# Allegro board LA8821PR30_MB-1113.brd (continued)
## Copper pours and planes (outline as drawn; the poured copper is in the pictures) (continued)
LG_5V on IN3 (solid shape): 199.07,56.32 199.07,55.16 198,54.09 195.78,54.09 195.78,55.02 195.85,55.09 196.77,55.09 196.83,55.15 196.88,55.16 196.93,55.17 196.99,55.19 197.04,55.21 197.08,55.25 197.12,55.29 197.15,55.33 197.16,55.35 197.95,55.35 197.95,55.29 197.96,55.24 197.97,55.19 198,55.14 198.03,55.1 198.06,55.06 198.1,55.02 198.15,55 198.2,54.98 198.25,54.97 198.3,54.96 198.36,54.97 198.41,54.98 198.46,55 198.51,55.02 198.55,55.06 198.58,55.1 198.61,55.14 198.64,55.19 198.65,55.24 198.66,55.29 198.66,55.35 198.65,55.4 198.64,55.45 198.61,55.5 198.58,55.54 198.55,55.58 198.51,55.61 198.46,55.64 198.41,55.66 198.36,55.67 198.3,55.68 198.25,55.67 198.2,55.66 198.15,55.64 198.1,55.61 198.06,55.58 198.03,55.54 198,55.5 197.97,55.45 197.96,55.4 197.95,55.35 197.16,55.35 197.18,55.38 197.2,55.44 197.21,55.49 197.21,55.54 197.34,55.66 197.34,56.73 197.49,56.88 198.51,56.88
LG_+V1.05S_VCCPP on TOP (solid shape): 117.74,49.85 117.74,48.17 117.53,47.97 117.28,47.97 116.72,48.53 116.26,48.53 116.11,48.68 116.11,49.8 116.42,50.1 117.48,50.1
LG_+V1.05S_VCCPP on TOP (solid shape): 124.31,45.35 124.31,44.63 124.23,44.54 124.23,43.94 124.06,43.78 123.27,43.78 123.07,43.98 123.07,45 123.5,45.43 124.24,45.43
LG_+V1.05S_VCCPP on IN4 (solid shape): 124.34,44.89 124.34,43.93 124.19,43.78 123.07,43.78 122.89,43.95 122.89,45.28 123.07,45.45 123.78,45.45
LG_+V1.05S_VCCPP on IN4 (solid shape): 116.91,49.73 117.42,49.73 117.58,49.57 117.58,49.06 117.74,48.91 117.74,48.63 117.66,48.55 116.19,48.55 116.09,48.65 116.09,49.57 116.26,49.75 116.9,49.75
LGATE on TOP (solid shape): 139.88,32.73 139.88,31.48 138.46,31.48 138.28,31.66 138.28,32.68 138.49,32.88 139.73,32.88
LGATE on BOTTOM (solid shape): 147.25,35.94 147.25,35.09 147.17,35.01 146.57,35.01 146.47,35.09 146.35,35.17 146.01,35.52 146.01,35.93 146.12,36.04 147.15,36.04
LGATE on IN4 (solid shape): 140.49,33.49 140.49,32.83 139.91,32.25 138.56,32.25 138.39,32.42 138.39,32.7 139.38,33.69 140.29,33.69
LGATE on IN4 (solid shape): 146.92,35.67 146.92,35.14 146.21,34.43 145.73,34.43 145.5,34.66 145.5,35.42 145.65,35.57 145.67,35.58 145.86,35.68 145.96,35.87 145.96,35.89 146.13,36.06 146.54,36.06
LGATE1 on TOP (solid shape): 25.71,65.49 26.85,65.49 26.98,65.37 26.98,65.11 26.6,64.73 24.57,64.73 24.49,64.81 24.49,65.39 24.85,65.75 25.46,65.75
LGATE1 on BOTTOM (solid shape): 24.72,78.5 24.72,77.33 25.48,76.57 25.48,76.21 25.36,76.09 25.05,76.09 24.87,76.26 24.87,76.62 24.65,76.85 24.65,76.97 24.47,77.15 24.47,78.52 24.49,78.55 24.67,78.55
LGATE1 on IN2 (solid shape): 26.47,65.49 26.47,64.86 26.19,64.58 24.65,64.58 24.49,64.73 24.49,65.54 24.57,65.62 26.35,65.62
LGATE1 on IN2 (solid shape): 26.04,75.98 26.04,75.4 25.79,75.15 25.13,75.15 24.87,75.4 24.87,76.64 24.65,76.87 24.65,77.08 24.7,77.13 24.9,77.13
LGATE1G on TOP (solid shape): 24.85,69.94 24.85,69.18 24.75,69.08 24.62,69.08 24.19,68.64 23.53,68.64 23.32,68.85 23.32,69.86 23.5,70.04 24.75,70.04
LGATE1G on BOTTOM (solid shape): 20.07,80.3 20.12,80.3 20.15,80.3 20.17,80.29 20.39,80.06 21.53,80.06 21.57,80.02 21.57,79.9 21.5,79.82 19.97,79.82 19.59,79.44 19.36,79.44 19.26,79.54 19.26,79.79 19.77,80.3 20.02,80.3
LGATE1G on IN2 (solid shape): 24.85,70.98 24.85,69.63 24.49,69.28 23.48,69.28 23.35,69.41 23.35,70.7 23.76,71.11 24.72,71.11
LGATE1G on IN2 (solid shape): 20.48,80.18 21.77,80.18 21.85,80.1 21.85,79.44 21.77,79.36 19.39,79.36 19.21,79.54 19.21,79.79 19.69,80.28 20.38,80.28
LX_3V on TOP (solid shape): 189.78,56.41 189.78,56.09 190.02,55.84 191.09,55.84 191.19,55.74 192.49,55.74 192.56,55.66 192.56,55.56 192.49,55.49 191.17,55.49 191.04,55.36 189.2,55.36 189.11,55.45 189.11,56.4 189.14,56.43 189.77,56.43
LX_3V on TOP (solid shape): 193.83,63.09 193.83,61.26 193.72,61.15 192.56,61.15 192.29,60.87 192.29,60.26 192.18,60.15 191.81,60.13 191.78,59.76 191.27,59.25 188.83,59.25 188.75,59.32 188.75,62.06 188.67,62.14 188.67,63.5 189,63.82 193.1,63.82
LX_3V on BOTTOM (solid shape): 193.91,63.16 193.91,59.17 193.81,59.07 190.43,59.07 190.38,59.12 190.38,63.18 191.02,63.82 193.25,63.82
LX_3V on IN1 (solid shape): 192.44,61.76 192.44,61.28 192.21,61.05 191.14,61.05 190.89,60.79 190.33,60.79 190.2,60.92 190.2,61.66 190.43,61.89 192.31,61.89
LX_3V on IN1 (solid shape): 189.29,57.44 189.29,56.91 189.77,56.43 189.77,56.06 189.95,55.88 191.04,55.88 191.17,55.75 191.17,55.45 191.12,55.4 189.38,55.4 188.35,56.43 188.35,57.39 188.5,57.54 189.19,57.54
LX_5V on TOP (solid shape): 197.42,55.31 197.77,55.31 198.15,54.93 198.15,54.47 198.03,54.34 197.29,54.34 197.21,54.42 197.21,54.93 196.88,55.26 195.99,55.26 195.74,55.51 194.55,55.51 194.52,55.54 194.52,55.71 194.57,55.77 196.96,55.77
LX_5V on TOP (solid shape): 203.91,65.07 203.91,59.06 203.58,58.74 200.31,58.74 200.3,58.75 199.23,58.75 199.04,58.94 199.04,59.75 199.7,60.41 199.7,61.94 200.08,62.32 201.02,62.32 201.52,62.81 201.52,65.07 201.79,65.34 203.64,65.34
LX_5V on BOTTOM (solid shape): outline of 89 points within 196.07,58.7 202.2,66.93
LX_5V on IN1 (solid shape): 200.26,59.8 200.26,58.51 200.57,58.2 200.57,57.65 200.39,57.47 200.16,57.47 199.8,57.82 199.8,59.83 199.88,59.91 200.16,59.91
LX_5V on IN1 (solid shape): 199.17,56.65 199.17,56.1 198.76,55.69 198.24,55.69 198.2,55.68 198,55.54 197.94,55.3 197.91,55.23 197.84,55.19 196.03,55.19 195.88,55.35 195.88,55.7 195.98,55.8 196.9,55.8 198.1,57.01 198.81,57.01
N_5V_001 on TOP (solid shape): 206.44,58.84 206.44,57.59 206.12,57.27 203.24,57.27 203.08,57.11 203.08,56.97 202.46,56.34 201.71,56.34 201.58,56.48 201.58,57.98 201.74,58.14 204.37,58.14 205.43,59.19 206.09,59.19
P1 on TOP (solid shape): 142.02,43.04 142.02,40.88 141.84,40.7 135.54,40.7 135.39,40.86 135.39,43.35 135.59,43.55 141.51,43.55
P1 on TOP (solid shape): 155.94,42.84 155.94,38.87 155.89,38.82 155.43,38.82 155.39,38.84 155.38,38.87 155.38,40.2 155.02,40.55 154.67,40.2 154.67,38.87 154.59,38.8 154.01,38.8 153.85,38.95 153.85,42.89 154.11,43.14 155.63,43.14
P1 on IN3 (solid shape): outline of 1605 points within 138.74,33.31 156.01,43.52
PHASE on TOP (solid shape): 141.01,36.57 141.01,35.14 141,35.14 141,34.93 140.74,34.66 140.42,34.66 139.79,34.03 139.79,33.51 139.42,33.14 138.42,33.14 137.7,32.42 137.7,28.02 137.34,27.65 133.23,27.65 133.07,27.81 133.07,28.95 132.71,29.32 130.83,29.32 130.51,29.64 130.51,31.47 130.72,31.68 133.02,31.68 133.07,31.74 133.07,32.39 133.37,32.69 133.99,32.69 134.56,33.26 137.7,33.26 137.86,33.42 137.86,36.59 138,36.73 140.85,36.73
PHASE on BOTTOM (solid shape): 145.19,36.84 146.87,36.84 146.95,36.77 146.95,36.64 146.9,36.59 145.85,36.59 145.54,36.28 145.53,36.28 145.36,36.18 145.26,36.01 145.26,35.99 145.14,35.88 144.71,35.88 144.56,36.03 144.56,36.82 144.66,36.92 145.12,36.92
PHASE on BOTTOM (solid shape): outline of 152 points within 132.11,29.38 142.23,36.93
PHASE on IN1 (solid shape): 141.15,36.54 141.15,35.14 140.77,34.76 140.01,34.76 137.22,31.97 134.68,31.97 134.42,32.22 134.42,33.36 137.85,36.79 140.9,36.79
PHASE on IN2 (solid shape): 141.15,36.54 141.15,35.14 140.77,34.76 140.01,34.76 137.22,31.97 134.68,31.97 134.42,32.22 134.42,33.36 137.85,36.79 140.9,36.79
PHASE on IN4 (solid shape): 141.15,36.54 141.15,35.14 140.77,34.76 140.01,34.76 137.22,31.97 134.68,31.97 134.42,32.22 134.42,33.36 137.85,36.79 140.9,36.79
PHASE1 on TOP (solid shape): 30.03,69.05 30.03,64.45 28.9,63.32 28.9,59.66 28.51,59.27 26.73,59.27 26.47,59.52 26.47,60.87 26.22,61.13 24.24,61.13 23.98,61.38 23.98,64.15 24.15,64.31 26.69,64.31 27.36,64.99 27.36,69.23 27.39,69.25 29.83,69.25
PHASE1 on BOTTOM (solid shape): 25.1,78.52 25.1,77.64 25.16,77.58 25.16,77.57 25.21,77.49 25.29,77.44 25.3,77.43 25.33,77.41 25.94,77.41 26.88,76.47 26.88,75.83 26.8,75.75 25.87,75.75 25.76,75.86 25.76,76.57 25.28,77.05 25.28,77.13 24.85,77.56 24.85,78.55 24.87,78.57 25.05,78.57
PHASE1 on BOTTOM (solid shape): 28.35,64.73 28.35,61.51 29.17,61.51 29.17,64 29.24,64.07 30.49,64.07 30.56,64 30.56,59.4 30.16,58.99 26.6,58.99 26.47,59.12 26.47,60.7 26.24,60.93 26.05,61.13 24.21,61.13 23.98,61.35 23.98,64.15 24.19,64.35 26.47,64.35 26.98,64.86 28.23,64.86
PHASE1 on IN1 (solid shape): 28.33,65.42 28.33,64.38 28.15,64.2 27.21,64.2 26.68,64.73 26.68,65.62 26.75,65.7 28.05,65.7
PHASE1 on IN1 (solid shape): 26.88,76.49 26.88,75.7 26.75,75.58 26.3,75.58 25.71,76.16 25.71,76.64 25.25,77.1 25.25,77.23 25.43,77.41 25.97,77.41
PHASE1G on TOP (solid shape): 23.65,73.62 23.65,71.41 23.22,70.98 23.17,70.98 23.17,70.93 23.1,70.85 23.1,64.76 22.97,64.63 21.65,64.63 21.64,64.67 21.5,64.88 21.26,64.96 21.24,64.96 21.19,65.01 20.38,65.01 20.28,65.11 20.28,68.92 19.41,69.79 19.41,70.07 19.44,70.09 19.44,71.92 19.26,72.1 19.26,72.38 19.39,72.5 19.87,72.5 19.98,72.62 19.98,73.36 20.4,73.77 23.5,73.77
PHASE1G on BOTTOM (solid shape): 21.58,79.62 21.58,79.49 21.51,79.42 20.36,79.42 19.69,78.75 19.69,77.81 19.64,77.76 19.64,77.76 19.23,77.36 18.32,77.36 18.26,77.42 18.26,79.03 18.42,79.2 19.64,79.2 20.1,79.66 21.54,79.66
PHASE1G on BOTTOM (solid shape): 24.29,73.19 24.29,70.8 23.04,69.56 23.04,67.22 23.02,67.2 21.72,67.2 21.67,67.25 21.67,69.71 21.62,69.76 20.89,69.76 20.86,69.74 20.86,67.25 20.78,67.17 19.41,67.17 19.13,67.45 19.13,71.13 18.96,71.31 18.65,71.31 18.45,71.51 18.45,72.99 18.63,73.16 19.87,73.16 20.48,73.77 23.71,73.77
PHASE1G on IN1 (solid shape): 22.41,73.88 22.41,72.66 22.28,72.53 22,72.53 21.88,72.66 21.34,72.66 21.14,72.86 21.14,73.77 21.37,74 22.28,74
PHASE1G on IN1 (solid shape): 21.8,79.82 21.8,79.39 21.48,79.07 19.98,79.07 19.79,78.88 19.79,78.17 19.57,77.94 19.26,77.94 19.11,78.09 19.11,79.14 19.21,79.24 19.66,79.24 20.07,79.65 20.41,79.65 20.81,80.05 21.57,80.05
SGATE on TOP (solid shape): 155.03,35.25 155.03,34.07 154.98,34.02 154.21,34.02 154.13,34.1 154.13,35.24 154.24,35.34 154.93,35.34
SGATE on BOTTOM (solid shape): 145.73,38.01 146.9,38.01 146.95,37.96 146.95,37.83 146.9,37.78 145.63,37.78 145.34,38.07 144.9,38.07 144.76,38.21 144.76,38.52 144.84,38.6 145.14,38.6
SGATE on IN4 (solid shape): 155.25,36.49 155.25,34.94 155.1,34.79 154.24,34.79 154.11,34.91 154.11,36.51 154.29,36.69 155.05,36.69
SGATE on IN4 (solid shape): 146.41,38.85 146.41,37.91 146.31,37.81 145.04,37.81 144.76,38.09 144.76,38.49 144.86,38.6 145.21,38.6 145.22,38.59 145.35,38.57 145.48,38.59 145.48,38.6 145.55,38.6 145.88,38.93 146.34,38.93
SW_1.35V on TOP (solid shape): 56.43,22.65 56.43,21.32 56.17,21.06 55.47,21.06 55.18,20.76 51.95,20.76 50.78,21.93 49.16,21.93 49.05,22.03 49.05,23.71 49.98,24.64 50.82,24.64 51.14,24.96 54.12,24.96
SW_1.35V on TOP (solid shape): 33.37,21.22 33.37,20.63 33.59,20.41 33.6,20.41 33.68,20.32 34.4,20.32 34.59,20.13 35.26,20.13 35.39,20 35.39,19.09 35.24,18.94 33.27,18.94 32.67,19.54 32.67,20.99 32.6,21.07 32.44,21.07 32.37,21.15 32.37,21.25 32.42,21.3 33.29,21.3
SW_1.35V on BOTTOM (solid shape): 53.8,24.45 53.8,19.27 53.78,19.27 53.4,18.88 48.95,18.88 48.44,19.39 48.44,24.6 48.57,24.73 53.52,24.73
SW_1.35V on IN2 (solid shape): 51.21,24.4 51.21,23.33 50.5,22.62 49.97,22.62 49.64,22.95 49.64,23.79 50.4,24.55 51.06,24.55
SW_1.35V on IN2 (solid shape): 35.9,19.72 35.9,19.04 35.75,18.89 33.99,18.89 32.93,19.95 32.93,20.18 33.18,20.43 35.19,20.43
SW_+V1.05S_VCCPP on TOP (solid shape): 125.38,45.28 125.38,44.44 125.56,44.26 125.56,42.23 125.43,42.1 124.7,42.1 124.57,42.23 124.57,42.94 125.08,43.45 125.08,44.51 125,44.59 125,45.35 125.05,45.4 125.25,45.4
SW_+V1.05S_VCCPP on TOP (solid shape): 115.68,49.19 115.68,48.91 116.29,48.3 116.64,48.3 117.53,47.41 121.42,47.41 121.77,47.05 121.77,42.8 121.58,42.61 116.14,42.61 115.77,42.98 115.77,44.4 115.25,44.92 115.25,46.77 115.07,46.95 112.17,46.95 111.98,47.14 111.98,49.28 112.33,49.62 115.25,49.62
SW_+V1.05S_VCCPP on BOTTOM (solid shape): 115.98,48.37 118.75,48.37 120.1,47.03 120.1,43.85 120.43,43.52 124.39,43.52 124.52,43.65 124.52,44.16 124.77,44.41 125.41,44.41 125.53,44.28 125.53,42.89 125.03,42.38 121.98,42.38 121.6,42 118.29,42 117.63,41.33 114.58,41.33 114.36,41.55 114.36,46.75 114.1,47 113.29,47 113.11,47.18 113.11,47.99 113.44,48.32 114.94,48.32 115.2,48.58 115.78,48.58
UG_3V on TOP (solid shape): 191.37,56.15 192.49,56.15 192.56,56.07 192.56,55.94 192.51,55.89 191.24,55.89 191.12,56.02 190.13,56.02 190.02,56.12 190.02,56.43 190.13,56.53 190.99,56.53
UG_3V on TOP (solid shape): 194.19,60.44 194.72,60.44 194.72,60.44 195.13,60.44 195.23,60.34 195.23,59.83 195.11,59.7 195.1,59.7 195,59.63 194.93,59.53 194.92,59.52 194.61,59.21 193.02,59.21 192.79,59.44 192.79,60.77 192.8,60.78 192.94,60.93 193.7,60.93
UG_3V on IN1 (solid shape): 191.14,56.58 191.14,56.1 191.09,56.05 190.13,56.05 189.97,56.2 189.97,56.6 189.54,57.04 189.54,57.34 189.62,57.42 190.3,57.42
UG_3V on IN1 (solid shape): 195.23,60.29 195.23,59.86 195.04,59.67 195.01,59.64 194.97,59.6 192.59,59.6 192.21,59.22 191.83,59.22 191.8,59.25 191.8,60.36 191.9,60.46 195.05,60.46
UG_5V on TOP (solid shape): 201.28,63.69 201.28,62.91 200.87,62.5 200.11,62.5 200.01,62.6 200.01,63.74 200.39,64.12 200.84,64.12
UG_5V on TOP (solid shape): 196.91,56.3 196.91,56.05 196.81,55.94 195.74,55.94 195.69,55.89 194.6,55.89 194.52,55.97 194.52,56.12 194.57,56.17 195.69,56.17 195.92,56.4 196.81,56.4
UG_5V on IN1 (solid shape): 196.93,57.06 196.93,56.15 196.76,55.97 195.92,55.97 195.79,56.1 195.79,57.04 195.94,57.19 196.81,57.19
UG_5V on IN1 (solid shape): 201.23,63.61 201.23,63.26 200.21,62.24 199.65,62.24 199.45,62.45 199.45,62.93 200.16,63.64 201.2,63.64
UG_+V1.05S_VCCPP on TOP (solid shape): 111.79,49.52 111.79,47.13 111.64,46.98 110.57,46.98 110.37,47.18 110.37,49.44 110.55,49.62 111.69,49.62
UG_+V1.05S_VCCPP on TOP (solid shape): 125.81,45.35 125.81,44.64 126.04,44.41 126.88,44.41 127.01,44.28 127.01,43.75 126.73,43.47 125.97,43.47 125.74,43.69 125.74,44.25 125.74,44.26 125.74,44.34 125.51,44.56 125.51,45.3 125.58,45.38 125.79,45.38
UG_+V1.05S_VCCPP on IN4 (solid shape): 111.78,47.43 111.78,46.15 111.54,45.91 110.52,45.91 110.34,46.09 110.34,47.41 110.52,47.59 111.63,47.59
UG_+V1.05S_VCCPP on IN4 (solid shape): 127.18,44.28 127.18,43.14 127.06,43.01 125.89,43.01 125.79,43.12 125.79,44.28 126.04,44.54 126.93,44.54
UGATE on TOP (solid shape): 140.9,38.09 140.9,37.15 140.79,37.03 138.55,37.03 138.49,37.1 138.49,38.01 138.72,38.24 140.75,38.24
UGATE on BOTTOM (solid shape): 145.4,37.22 146.87,37.22 146.95,37.15 146.95,37.05 146.9,37 145.3,37 145.22,37.07 144.33,37.07 144.15,37.25 144.15,37.43 144.25,37.53 145.09,37.53
UGATE on IN4 (solid shape): 141.71,38.14 141.71,37.12 141.59,37 140.06,37 139.91,37.15 139.91,38.06 140.04,38.19 141.66,38.19
UGATE on IN4 (solid shape): 145.3,37.45 145.3,36.79 145.09,36.59 143.44,36.59 143.36,36.66 143.36,37.5 143.52,37.66 145.09,37.66
UGATE1 on TOP (solid shape): 34.09,67.27 34.09,66.14 33.94,65.99 32.97,65.99 32.85,66.1 32.85,67.17 33.08,67.4 33.97,67.4
UGATE1 on BOTTOM (solid shape): 26.04,77.99 26.55,77.99 27.11,77.43 27.11,77.18 26.98,77.05 26.51,77.05 25.95,77.61 25.33,77.61 25.28,77.66 25.28,78.5 25.33,78.55 25.48,78.55
UGATE1 on IN1 (solid shape): 27.71,77.54 27.71,76.68 27.59,76.56 27.07,76.56 25.95,77.68 25.95,77.82 26.18,78.06 27.19,78.06
UGATE1 on IN1 (solid shape): 34.39,68.88 34.39,67.13 34.14,66.89 32.93,66.89 32.79,67.03 32.79,68.62 32.83,68.66 32.82,68.67 32.82,69.05 32.95,69.18 34.09,69.18
UGATE1G on TOP (solid shape): 17.96,73.6 17.96,71.59 17.84,71.46 16.82,71.46 16.69,71.59 16.69,74.05 16.87,74.23 17.33,74.23
UGATE1G on BOTTOM (solid shape): 21.57,79.21 21.57,79.08 21.55,79.06 20.61,79.06 20.38,78.83 20.38,77.79 20.3,77.71 20.1,77.71 19.93,77.88 19.93,78.75 20.44,79.26 21.52,79.26
UGATE1G on IN1 (solid shape): 17.37,73.86 17.37,72.24 17.22,72.09 16.23,72.09 16.07,72.24 16.07,73.81 16.2,73.94 17.29,73.94
UGATE1G on IN1 (solid shape): 20.53,78.85 20.53,77.31 19.99,76.77 19.57,76.77 19.03,77.3 19.03,77.46 19.34,77.76 19.77,77.76 19.96,77.95 19.96,78.78 20.08,78.91 20.47,78.91
VCOMP1 on TOP (solid shape): 128.98,38.74 128.98,36.78 127.67,35.47 126.3,35.47 126.27,35.47 126.22,35.46 126.17,35.45 126.12,35.42 126.07,35.39 126.03,35.36 126,35.32 125.97,35.27 125.95,35.22 125.94,35.17 125.94,35.12 125.94,35.06 125.95,35.01 125.97,34.96 126,34.91 126.03,34.87 126.07,34.84 126.12,34.81 126.17,34.78 126.22,34.77 126.27,34.76 126.3,34.76 127.69,34.76 127.69,34.1 121.11,34.1 120.25,34.96 118.39,34.96 118.39,35.18 118.38,35.25 118.37,35.33 118.34,35.4 118.31,35.47 118.28,35.53 118.23,35.59 118.21,35.62 118.21,36.07 118.44,36.31 118.75,36.31 118.99,36.55 125.46,36.55 125.46,38.15 124.44,38.15 124.44,36.55 118.99,36.55 119.56,37.12 119.56,38.54 120.28,39.26 128.45,39.26
VCOMP1 on BOTTOM (solid shape): 120.38,40.02 120.38,37.53 120.4,37.5 120.4,35.19 120.01,34.8 117.75,34.8 117.23,35.32 117.23,36.18 116.92,36.49 117.53,36.49 117.53,36.46 117.54,36.4 117.56,36.35 117.58,36.3 117.61,36.25 117.65,36.21 117.69,36.18 117.74,36.15 117.79,36.13 117.84,36.11 117.9,36.11 117.96,36.11 118.01,36.12 118.06,36.14 118.11,36.16 118.16,36.19 118.2,36.23 118.23,36.28 118.26,36.32 118.28,36.38 118.29,36.43 118.3,36.49 118.29,36.54 118.28,36.6 118.26,36.65 118.23,36.7 118.2,36.74 118.16,36.78 118.11,36.81 118.06,36.84 118.01,36.86 117.96,36.87 117.9,36.87 117.84,36.86 117.79,36.85 117.74,36.83 117.69,36.8 117.65,36.76 117.61,36.72 117.58,36.67 117.56,36.62 117.54,36.57 117.53,36.52 117.53,36.49 116.92,36.49 116.48,36.93 114.02,36.93 114.01,36.96 113.98,37.01 113.94,37.06 113.89,37.09 113.87,37.11 113.87,38.98 113.95,39.06 115.58,39.06 116.9,40.37 120.02,40.37
VLDOIN_1.35V on TOP (solid shape): 35.41,23.5 35.41,21.79 35.28,21.66 34.74,21.66 34.13,22.27 32.44,22.27 32.37,22.33 32.37,22.44 32.42,22.48 33.68,22.48 34.11,22.92 34.11,23.85 34.19,23.93 34.98,23.93
N3514555 on BOTTOM (solid shape): 182.66,68.29 182.66,66.59 182.76,66.48 185.94,66.48 186.87,67.42 193.73,67.42 193.96,67.2 193.96,64.2 193.78,64.02 190.81,64.02 190.25,63.46 190.25,60.72 189.75,60.21 185.66,60.21 185.6,60.16 185.12,60.16 183.98,61.3 181.34,61.3 181.27,61.37 181.27,68.99 181.36,69.08 181.87,69.08
N6573945 on TOP (solid shape): 135.21,43.57 135.21,40.09 135.39,39.91 141.19,39.91 141.35,39.75 141.35,38.66 141.35,38.66 141.35,38.51 141.26,38.42 138.29,38.42 137.66,37.79 137.66,33.63 137.49,33.47 134.5,33.47 134.16,33.13 133.54,33.13 133.53,33.12 132.31,33.12 132.11,33.31 132.11,34.56 131.88,34.79 131.38,34.79 131.22,34.94 131.22,36.18 131.43,36.38 132.71,36.38 132.9,36.56 132.9,43.27 133.33,43.7 135.09,43.7
N18687912 on BOTTOM (solid shape): 205.65,68.81 211.88,68.81 211.98,68.71 211.98,67.88 211.69,67.59 211.69,66.03 207.6,61.94 207.6,61.15 207.04,60.59 207.04,58.89 206.92,58.76 203.74,58.76 202.27,60.24 202.27,65.52 202.83,66.08 202.83,68.87 202.98,69.03 205.43,69.03
N21241055 on TOP (solid shape): 157.59,37.71 157.59,34.61 157.28,34.3 156.06,34.3 155.79,34.02 155.27,34.02 155.25,34.05 155.25,35.43 155.24,35.43 155.16,35.52 154.17,35.52 154.13,35.57 154.13,37.81 154.14,37.82 154.67,37.82 154.67,36.44 155.02,36.08 155.38,36.44 155.38,37.91 157.39,37.91
N21884322 on TOP (solid shape): 97.34,51.52 97.34,50.95 97.09,50.7 94.55,50.7 94.29,50.95 94.29,51.71 94.42,51.84 97.02,51.84
N21884322 on BOTTOM (solid shape): outline of 135 points within 92.64,48.35 99.63,53.28
N21900089 on TOP (solid shape): 157.59,33.92 157.59,33.24 157.39,33.03 154.57,33.03 154.41,33.19 154.41,33.62 154.57,33.77 156.01,33.77 156.22,33.97 157.54,33.97
N25021747 on BOTTOM (solid shape): 19.56,76.27 19.56,74.84 19.49,74.76 18.12,74.76 17.99,74.89 17.99,76.44 18.24,76.7 19.13,76.7
N25021757 on TOP (solid shape): 17.99,70.73 17.99,70.35 17.61,69.96 17.61,69.48 17.76,69.33 18.4,69.33 18.55,69.18 18.55,68.69 18.45,68.59 17.15,68.59 16.69,69.05 16.69,70.78 16.87,70.95 17.76,70.95
N28033400 on TOP (solid shape): 103.89,84.42 103.89,83.86 103.81,83.78 102.17,83.78 102.04,83.65 102.04,79.38 101.82,79.16 97.01,79.16 96.54,79.63 96.54,81.08 95.26,82.36 95.26,82.97 95.26,82.97 95.26,84.25 95.5,84.49 103.82,84.49
N28033400 on BOTTOM (solid shape): 102.11,84.75 102.11,80.67 101.01,79.57 96.78,79.57 96.65,79.69 96.65,82.08 96.27,82.46 96.05,82.46 96.05,82.47 95.73,82.47 95.69,82.51 95.69,83 96.05,83 96.05,83.02 96.22,83.02 96.22,83.72 96.05,83.72 96.05,83.75 95.69,83.75 95.69,84.2 96.05,84.2 96.05,84.22 96.22,84.22 96.22,84.92 96.05,84.92 96.05,84.95 95.69,84.95 95.69,85.12 95.69,85.16 95.69,85.46 95.71,85.48 101.38,85.48
N51743582 on TOP (solid shape): 161.35,43.4 161.35,38.82 161.75,38.42 162.41,38.42 163.01,37.82 163.01,33.53 162.85,33.36 157.92,33.36 157.84,33.44 157.84,37.86 157.54,38.16 156.5,38.16 156.22,38.44 156.22,43.42 156.37,43.57 161.17,43.57
N52558691 on BOTTOM (solid shape): 28.25,75.49 28.25,74.38 28.12,74.26 25.97,74.26 25.84,74.38 25.84,75.15 26.09,75.4 27.11,75.4 27.29,75.58 28.16,75.58
N52558937 on TOP (solid shape): 33.97,65.62 34.22,65.37 34.22,63.92 34.04,63.74 33.69,63.74 32.7,64.73 32.19,64.73 31.81,65.11 31.81,65.37 32.06,65.62 32.57,65.62
N75083074 on BOTTOM (solid shape): 105.32,61.96 105.32,61.35 105.52,61.15 105.52,61.11 105.54,61.08 105.54,60.97 105.47,60.9 103.92,60.9 103.78,61.03 103.79,61.06 103.79,61.13 103.77,61.2 103.77,61.21 103.77,61.46 103.91,61.6 103.97,61.64 104.01,61.7 104.4,62.09 105.19,62.09
N83744884 on BOTTOM (solid shape): 165.16,40.5 165.16,36.28 164.68,35.8 158.81,35.8 158.17,36.44 158.17,39.97 158.33,40.12 162.77,40.12 163,40.35 163,41.06 163.08,41.14 164.52,41.14
N84344604 on TOP (solid shape): 109.15,48.65 109.15,40.75 109,40.6 108.06,40.6 107.63,41.03 107.63,49.64 107.73,49.75 108.06,49.75
N84344604 on BOTTOM (solid shape): 109.94,47.13 109.96,47.13 111.01,46.09 113.65,46.09 113.86,45.87 113.86,40.77 113.7,40.6 107.75,40.6 107.37,40.98 107.37,46.21 107.4,46.33 107.37,46.45 107.37,47.08 108.13,47.84 109.23,47.84
N90173610 on TOP (solid shape): 206.16,75.79 207.61,75.79 207.98,75.41 207.98,73.13 207.08,72.22 204.4,72.22 204.32,72.3 204.32,75.72 204.4,75.79 206.16,75.79
N90173610 on BOTTOM (solid shape): 219.06,68.79 221.83,68.79 221.96,68.67 221.96,68.49 221.89,68.42 219.21,68.42 218.54,67.75 218.25,67.75 218.11,67.89 218.11,68.43 218.36,68.68 218.36,68.81 218.45,68.9 218.95,68.9
N90173610 on BOTTOM (solid shape): 210.5,74.74 210.5,73.49 210.24,73.24 207.69,73.24 206.55,72.1 205.77,72.1 205.49,72.38 205.49,74.42 205.96,74.89 210.34,74.89
N90173610 on IN3 (solid shape): 206.81,74.69 206.81,72.39 206.57,72.15 205.39,72.15 205.14,72.4 205.14,74.72 205.39,74.97 206.53,74.97
N90173610 on IN3 (solid shape): 219.22,70.01 219.22,68.19 218.74,67.71 218.2,67.71 217.94,67.98 217.94,69.79 218.33,70.19 219.04,70.19

Small or netless copper shapes (teardrops, artwork), in the pictures only: 11 on TOP, 26 on BOTTOM, 86 on IN2, 10 on IN3

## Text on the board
Ref Des/Silkscreen Bottom: H10 | H9 | H12 | H11 | H13 | CHA_DIS | 2 | CSO | 1
User.Comments: LA-8821P | 2013-11-14 | 2012-11-14 | QAZAO | Rita_Weng | REV:3.0(A02)
Ref Des/Silkscreen Top: H14 | CHB_DIS | B | A | CSO
GND4: GND4
GND5: GND5
BODY_CENTER: FIGURE | SIZE | 9.0 | 10.0 | 24.0 | 28.0 | 30.0 | 36.0 | 91.0 | 126.0 | 157.0 | 37.0 | 43.0 | 63.0 | 79.0 | 177.0 | 36.0x18.0 | 55.0x28.0 | 63.0x28.0 | 63.0x35.0 | 75.0x24.0 | 75.0x35.0 | 79.0x31.0 | 94.0x24.0 | 98.0x79.0 | DRILL CHART: TOP to BOTTOM | ALL UNITS ARE IN MILS | PLATED | NON-PLATED | QTY | 721 | 16 | 2198 | 10 | 9 | 1 | 5 | 2 | 3 | 26
USER_PART_NUM_TOP: FIGURE | SIZE | 8.0 | DRILL CHART: IN1 to IN4 | ALL UNITS ARE IN MILS | PLATED | QTY | 1122
DEVICE_TYPE_TOP: FIGURE | SIZE | 4.0 | DRILL CHART: TOP to GND1 | ALL UNITS ARE IN MILS | PLATED | QTY | 902 | 3
USER_PART_NUM_BOTTOM: FIGURE | SIZE | 4.0 | DRILL CHART: GND1 to IN1 | ALL UNITS ARE IN MILS | PLATED | QTY | 716
DEVICE_TYPE_BOTTOM: FIGURE | SIZE | 4.0 | DRILL CHART: IN4 to GND5 | ALL UNITS ARE IN MILS | PLATED | QTY | 967
COMPVAL_TYPE_BOTTOM: FIGURE | SIZE | 4.0 | DRILL CHART: GND5 to BOTTOM | ALL UNITS ARE IN MILS | PLATED | QTY | 1372 | 2
COMPVAL_TYPE_TOP: normal_1_2mm_2+8+2(TOP G-V IN1 G-V IN2 G-V G-V IN3 G-V IN4 G-V BOT)-120206.PDF | BOTTOM | GND5 | 5.5 | 4.1 | 4.8 | 3.6 | 3.7 | 2.8 | 4.8/3.2 | 3.6/2.8 | 2.8/3.7 | 3.7/4 | 4.5/5.7 | 4.1/6.5 | 2.8/7 | 3.5/5
User.28: IN3
